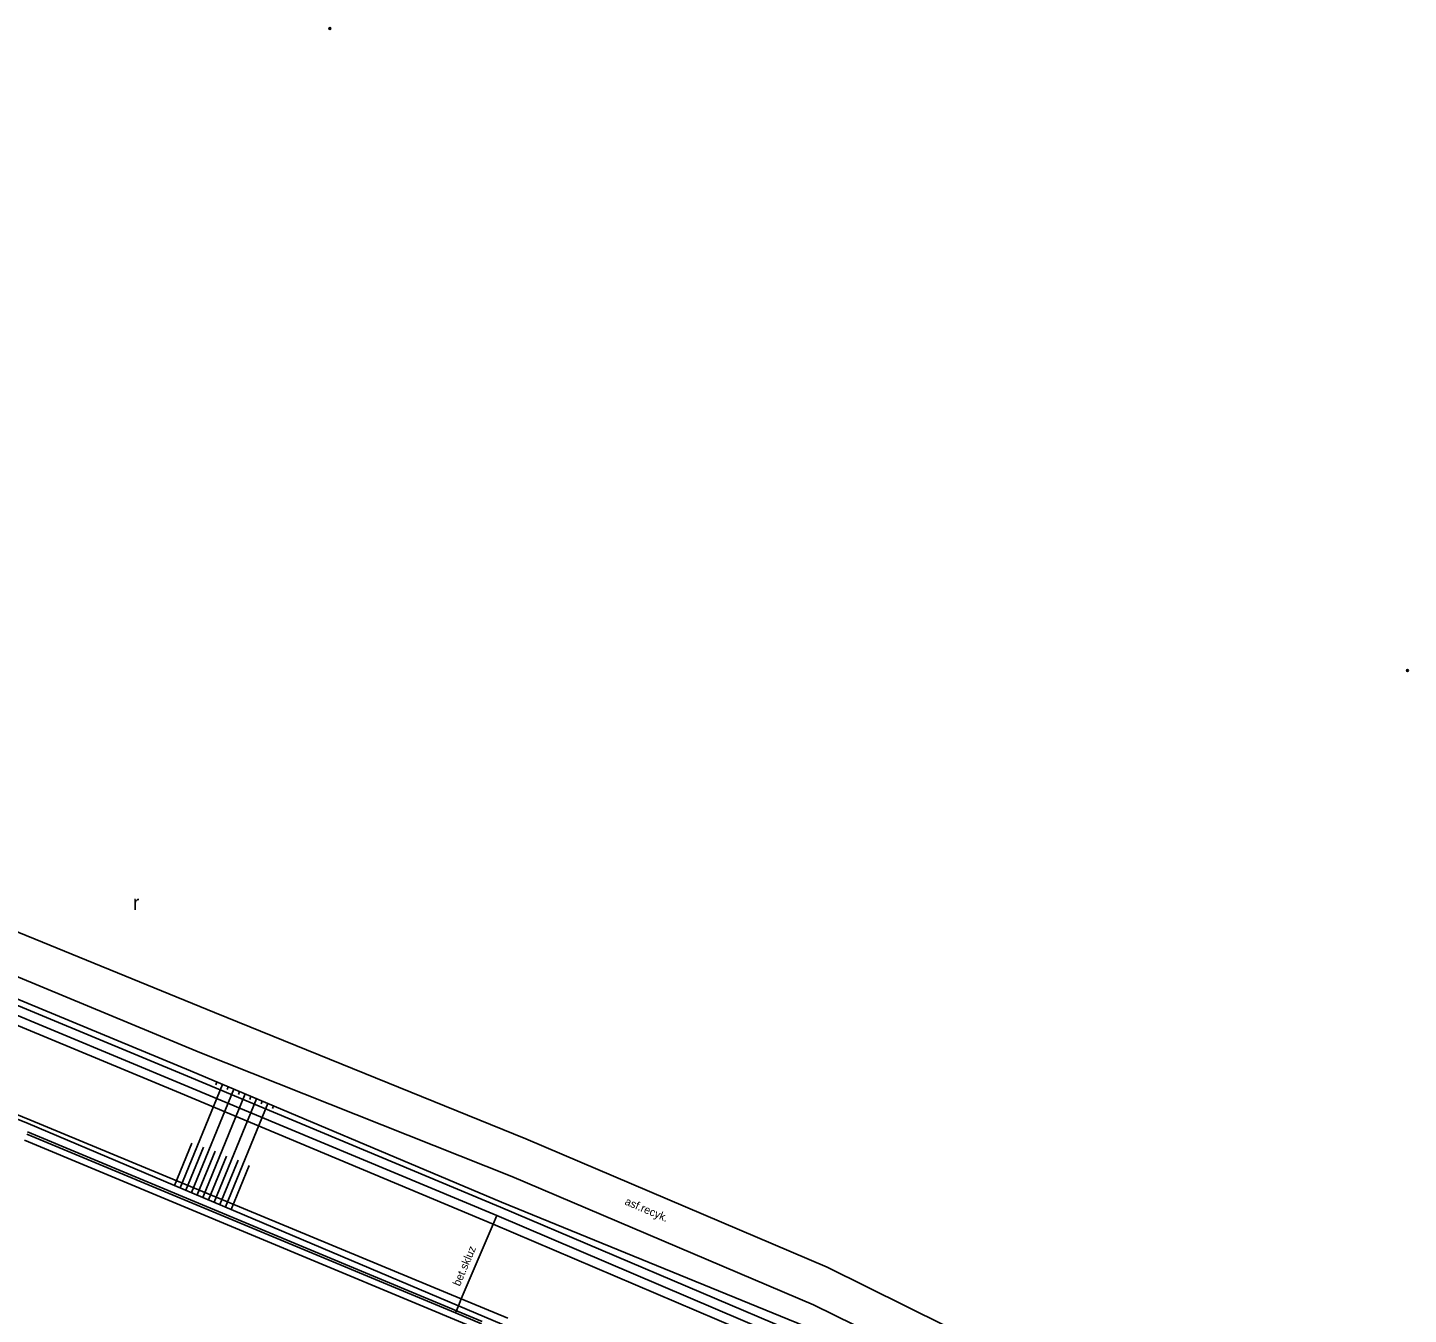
# Model space of a CAD drawing. Extents: x -539244 to -537359, y -1183785 to -1181851.
# Drawn here: x -538924.1 to -538811.7, y -1182612 to -1182507.3 of the extents above; entities that cross this region are included whole.
import ezdxf

# ---------------------------------------------------------------- set-up
doc = ezdxf.new("R2010")
doc.units = 0
for name, color, linetype in [('Vrstva 10', 7, 'Continuous'), ('Vrstva 11', 7, 'Continuous'), ('Vrstva 14', 7, 'Continuous'), ('Vrstva 15', 7, 'Continuous'), ('Vrstva 20', 7, 'Continuous'), ('Vrstva 36', 7, 'Continuous'), ('Vrstva 40', 7, 'Continuous'), ('Vrstva 7', 7, 'Continuous'), ('Vrstva 9', 7, 'Continuous')]:
    doc.layers.add(name, color=color, linetype=linetype)

msp = doc.modelspace()

# ---------------------------------------------------------------- linework, layer by layer
at = {"layer": 'Vrstva 10'}
msp.add_line((-538924.337, -1182597.828), (-538887.39, -1182613.259), dxfattribs=at)
at = {"layer": 'Vrstva 11'}
for p, q in [((-538908.866, -1182587.457), (-538928.016, -1182579.616)), ((-538928.918, -1182582.876), (-538910.064, -1182590.713)), ((-538929.83, -1182584.819), (-538911.066, -1182592.633)), ((-538930.402, -1182586.205), (-538911.644, -1182594.017)), ((-538883.537, -1182597.72), (-538908.866, -1182587.457)), ((-538910.064, -1182590.713), (-538884.673, -1182600.807)), ((-538911.066, -1182592.633), (-538885.61, -1182603.288)), ((-538911.644, -1182594.017), (-538886.196, -1182604.669)), ((-538859.01, -1182608.173), (-538883.537, -1182597.72)), ((-538884.673, -1182600.807), (-538860.122, -1182611.235)), ((-538885.61, -1182603.288), (-538861.117, -1182613.718)), ((-538886.196, -1182604.669), (-538861.725, -1182615.09)), ((-538835.249, -1182619.943), (-538859.01, -1182608.173)), ((-538860.122, -1182611.235), (-538836.673, -1182622.761))]:
    msp.add_line(p, q, dxfattribs=at)
msp.add_lwpolyline([(-538887.155, -1182612.777), (-538889.267, -1182611.896), (-538924.15, -1182597.347)], dxfattribs=at)
at = {"layer": 'Vrstva 14'}
for p, q in [((-538910.819, -1182592.191), (-538929.826, -1182584.311)), ((-538930.116, -1182585.512), (-538911.355, -1182593.325)), ((-538885.516, -1182602.878), (-538910.819, -1182592.191)), ((-538911.355, -1182593.325), (-538885.902, -1182603.979)), ((-538860.89, -1182612.942), (-538885.516, -1182602.878)), ((-538888.787, -1182610.766), (-538886.196, -1182604.669)), ((-538886.196, -1182604.669), (-538885.902, -1182603.979)), ((-538885.902, -1182603.979), (-538861.421, -1182614.404)), ((-538889.267, -1182611.896), (-538889.018, -1182611.31)), ((-538889.018, -1182611.31), (-538888.787, -1182610.766))]:
    msp.add_line(p, q, dxfattribs=at)
for points in [[(-538924.016, -1182596.476), (-538933.07, -1182592.832), (-538981.41, -1182573.377), (-539025.863, -1182555.486), (-539072.523, -1182536.706)], [(-538924.016, -1182596.476), (-538889.018, -1182611.31), (-538850.178, -1182627.773)]]:
    msp.add_lwpolyline(points, dxfattribs=at)
at = {"layer": 'Vrstva 15'}
for p, q in [((-538911.654, -1182601.716), (-538908.204, -1182593.296)), ((-538910.733, -1182602.106), (-538907.283, -1182593.685)), ((-538908.758, -1182593.331), (-538908.664, -1182593.101)), ((-538907.834, -1182593.711), (-538907.743, -1182593.49)), ((-538909.813, -1182602.496), (-538906.362, -1182594.074)), ((-538908.891, -1182602.887), (-538905.439, -1182594.463)), ((-538907.971, -1182603.277), (-538904.519, -1182594.852)), ((-538906.918, -1182594.116), (-538906.821, -1182593.88)), ((-538906.004, -1182594.521), (-538905.9, -1182594.268)), ((-538905.069, -1182594.875), (-538904.98, -1182594.657)), ((-538904.15, -1182595.272), (-538904.058, -1182595.047)), ((-538912.114, -1182601.521), (-538910.709, -1182598.092)), ((-538911.194, -1182601.911), (-538909.758, -1182598.405)), ((-538910.272, -1182602.301), (-538908.815, -1182598.744)), ((-538909.352, -1182602.691), (-538907.894, -1182599.134)), ((-538908.432, -1182603.082), (-538906.947, -1182599.459)), ((-538907.51, -1182603.472), (-538906.052, -1182599.914))]:
    msp.add_line(p, q, dxfattribs=at)
at = {"layer": 'Vrstva 20'}
for centre, radius in [((-538899.48, -1182507.37), 0.075), ((-538899.48, -1182507.37), 0.0204), ((-538811.8, -1182559.61), 0.075), ((-538811.8, -1182559.61), 0.0204)]:
    msp.add_circle(centre, radius, dxfattribs=at)
at = {"layer": 'Vrstva 7'}
for points in [[(-538923.885, -1182596.184), (-538932.935, -1182592.496), (-538981.188, -1182572.834), (-538998.012, -1182565.978)], [(-538885.009, -1182612.336), (-538888.787, -1182610.766), (-538923.885, -1182596.184)]]:
    msp.add_lwpolyline(points, dxfattribs=at)
at = {"layer": 'Vrstva 9'}
msp.add_line((-538887.078, -1182612.592), (-538924.073, -1182597.162), dxfattribs=at)

# ---------------------------------------------------------------- texts
at = {"layer": 'Vrstva 36'}
msp.add_text('r', height=1.2, dxfattribs=at).set_placement((-538915.51, -1182579.12))
at = {"layer": 'Vrstva 40'}
for s, rotation, p in [('asf.recyk.', 336.98671, (-538875.541, -1182603.056)), ('bet.skluz', 66.97282, (-538888.91, -1182609.778))]:
    msp.add_text(s, height=0.65, rotation=rotation, dxfattribs=at).set_placement(p)

doc.saveas('drawing.dxf')
